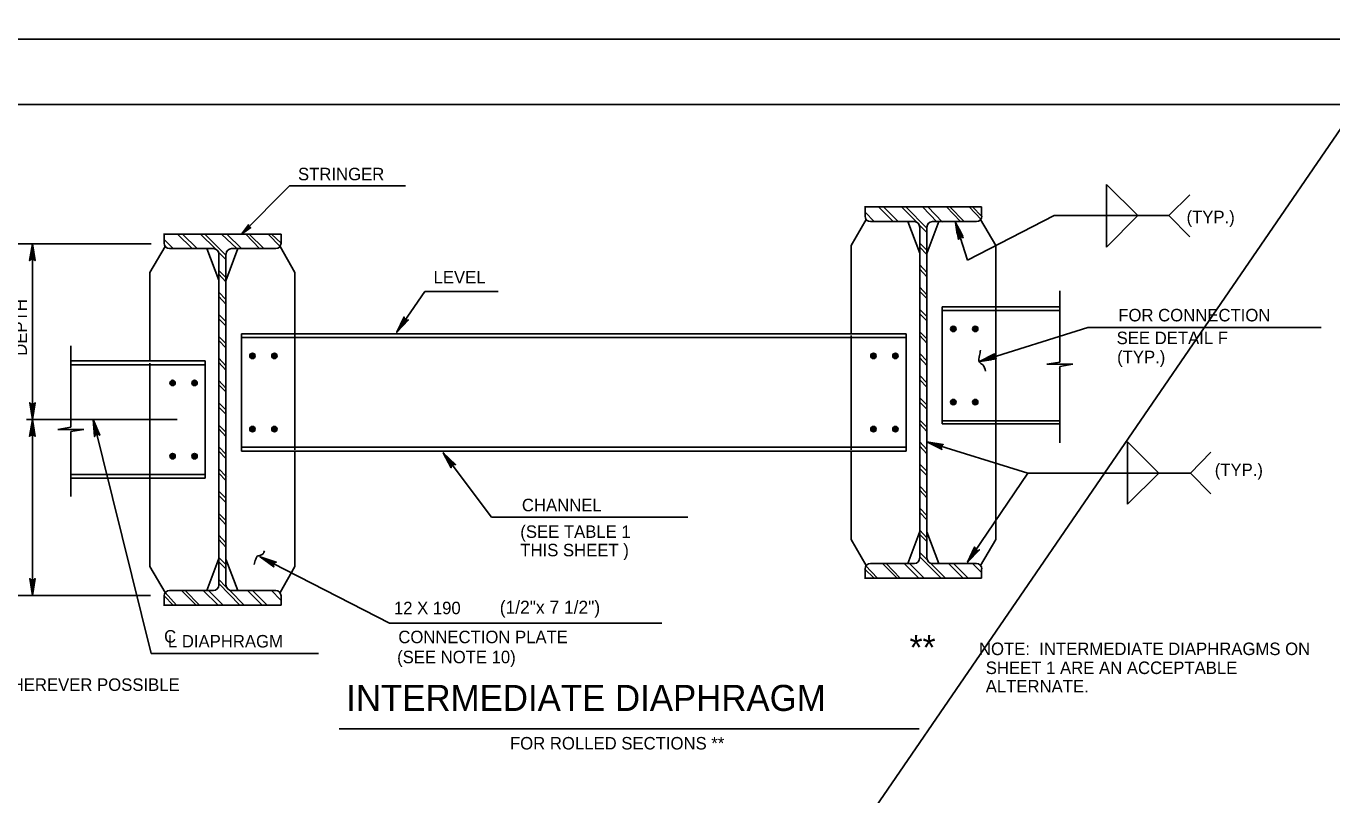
# Model space of a CAD drawing. Extents: x 634656 to 641360, y 298715 to 301183.
# Drawn here: x 640308.6 to 640609.6, y 299246 to 299423.1 of the extents above; entities that cross this region are included whole.
import ezdxf

# ---------------------------------------------------------------- set-up
doc = ezdxf.new("R2010")
doc.units = 0
for name, color, linetype in [('1', 7, 'Continuous'), ('2', 7, 'Continuous'), ('40', 7, 'Continuous')]:
    doc.layers.add(name, color=color, linetype=linetype)

msp = doc.modelspace()

# ---------------------------------------------------------------- linework, layer by layer
at = {"layer": '1'}
msp.add_line((641102.54, 300114.62), (640153.96, 298732.63), dxfattribs=at)
for points in [[(640309.53, 299369.26), (640309.79, 299369.4), (640309.99, 299372.95), (640309.53, 299369.26), (640309.36, 299369.07), (640309.99, 299372.95), (640310.16, 299369.4), (640310.43, 299369.27), (640309.99, 299372.95), (640310.6, 299369.07), (640310.43, 299369.27)], [(640396.47, 299355.35), (640396.17, 299355.38), (640393.99, 299352.58), (640396.47, 299355.35), (640396.71, 299355.41), (640393.99, 299352.58), (640395.87, 299355.59), (640395.72, 299355.85), (640393.99, 299352.58), (640395.69, 299356.12), (640395.72, 299355.85)], [(640310.45, 299336.14), (640310.18, 299336), (640309.99, 299332.45), (640310.45, 299336.14), (640310.61, 299336.33), (640309.99, 299332.45), (640309.81, 299336), (640309.55, 299336.13), (640309.99, 299332.45), (640309.37, 299336.33), (640309.55, 299336.13)], [(640309.53, 299328.76), (640309.79, 299328.9), (640309.99, 299332.45), (640309.53, 299328.76), (640309.36, 299328.57), (640309.99, 299332.45), (640310.16, 299328.9), (640310.43, 299328.77), (640309.99, 299332.45), (640310.6, 299328.57), (640310.43, 299328.77)], [(640324.43, 299328.76), (640324.65, 299328.96), (640323.99, 299332.45), (640324.43, 299328.76), (640324.32, 299328.54), (640323.99, 299332.45), (640325.01, 299329.05), (640325.3, 299328.99), (640323.99, 299332.45), (640325.52, 299328.83), (640325.3, 299328.99)], [(640406.58, 299321.59), (640406.71, 299321.86), (640404.74, 299324.83), (640406.58, 299321.59), (640406.56, 299321.34), (640404.74, 299324.83), (640407.01, 299322.09), (640407.29, 299322.14), (640404.74, 299324.83), (640407.56, 299322.09), (640407.29, 299322.14)], [(640365.56, 299298.74), (640365.56, 299299.04), (640362.49, 299300.83), (640365.56, 299298.74), (640365.66, 299298.51), (640362.49, 299300.83), (640365.73, 299299.37), (640365.97, 299299.54), (640362.49, 299300.83), (640366.22, 299299.61), (640365.97, 299299.54)], [(640310.45, 299295.64), (640310.18, 299295.5), (640309.99, 299291.95), (640310.45, 299295.64), (640310.61, 299295.83), (640309.99, 299291.95), (640309.81, 299295.5), (640309.55, 299295.63), (640309.99, 299291.95), (640309.37, 299295.83), (640309.55, 299295.63)]]:
    msp.add_lwpolyline(points, dxfattribs=at)
at = {"layer": '2'}
for p, q in [((640203.86, 299420.08), (641044.86, 299420.08)), ((640203.86, 299420.08), (641044.86, 299420.08)), ((640203.86, 299420.08), (641044.86, 299420.08)), ((640243.86, 299405.08), (641029.86, 299405.08)), ((640243.86, 299405.08), (641029.86, 299405.08)), ((640358.24, 299375.2), (640369.24, 299386.33)), ((640369.24, 299386.33), (640395.99, 299386.33)), ((640557.61, 299386.58), (640557.61, 299379.45)), ((640557.61, 299386.58), (640564.86, 299379.45)), ((640501.86, 299381.45), (640528.86, 299381.45)), ((640501.99, 299379.33), (640501.99, 299381.45)), ((640528.86, 299379.33), (640528.86, 299381.45)), ((640502.24, 299378.58), (640498.74, 299372.58)), ((640513.36, 299378.08), (640503.24, 299378.08)), ((640511.86, 299378.08), (640514.61, 299370.83)), ((640514.61, 299376.83), (640514.61, 299338.7)), ((640518.99, 299378.08), (640516.24, 299370.7)), ((640516.24, 299376.83), (640516.24, 299338.7)), ((640517.49, 299378.08), (640527.61, 299378.08)), ((640522.86, 299377.83), (640525.61, 299369.2)), ((640525.61, 299369.2), (640545.61, 299379.45)), ((640528.61, 299378.58), (640532.11, 299372.58)), ((640545.61, 299379.45), (640571.99, 299379.45)), ((640557.61, 299379.45), (640557.61, 299372.2)), ((640557.61, 299372.2), (640564.86, 299379.45)), ((640340.36, 299373.08), (640340.36, 299375.33)), ((640340.36, 299375.2), (640367.36, 299375.2)), ((640367.36, 299373.08), (640367.36, 299375.2)), ((640337.36, 299372.95), (640296.99, 299372.95)), ((640336.61, 299372.95), (640308.61, 299372.95)), ((640309.99, 299372.95), (640309.99, 299332.45)), ((640340.61, 299372.33), (640337.11, 299366.33)), ((640351.74, 299371.83), (640341.61, 299371.83)), ((640350.24, 299371.83), (640352.99, 299364.58)), ((640352.99, 299370.58), (640352.99, 299332.45)), ((640357.36, 299371.83), (640354.61, 299364.45)), ((640354.61, 299294.33), (640354.61, 299370.58)), ((640355.86, 299371.83), (640366.11, 299371.83)), ((640367.11, 299372.33), (640370.49, 299366.33)), ((640498.74, 299372.58), (640498.74, 299352.2)), ((640532.11, 299372.58), (640532.11, 299358.45)), ((640337.11, 299366.33), (640337.11, 299345.83)), ((640370.49, 299366.33), (640370.49, 299352.33)), ((640393.99, 299352.58), (640400.49, 299361.95)), ((640400.49, 299361.95), (640417.36, 299361.95)), ((640546.86, 299345.7), (640546.86, 299362.08)), ((640519.74, 299358.45), (640546.99, 299358.45)), ((640519.74, 299358.45), (640519.74, 299331.45)), ((640519.74, 299357.58), (640546.86, 299357.58)), ((640532.11, 299358.45), (640532.11, 299331.58)), ((640522.36, 299353.33), (640522.36, 299353.33)), ((640527.36, 299353.33), (640527.36, 299353.33)), ((640528.36, 299345.83), (640553.36, 299353.7)), ((640553.36, 299353.7), (640607.11, 299353.7)), ((640358.24, 299352.2), (640384.86, 299352.2)), ((640358.24, 299352.2), (640358.24, 299325.2)), ((640511.49, 299351.33), (640358.24, 299351.33)), ((640370.49, 299351.95), (640370.49, 299325.45)), ((640511.49, 299352.2), (640384.86, 299352.2)), ((640498.74, 299351.83), (640498.74, 299325.45)), ((640511.49, 299352.2), (640511.49, 299325.2)), ((640318.86, 299330.7), (640318.86, 299349.45)), ((640360.74, 299347.08), (640360.74, 299347.08)), ((640365.86, 299347.08), (640365.86, 299347.08)), ((640503.86, 299347.08), (640503.86, 299347.08)), ((640508.99, 299347.08), (640508.99, 299347.08)), ((640349.86, 299345.95), (640318.86, 299345.95)), ((640349.86, 299345.08), (640319.11, 299345.08)), ((640337.11, 299345.45), (640337.11, 299319.2)), ((640349.86, 299345.95), (640349.86, 299318.95)), ((640543.86, 299345.2), (640546.86, 299345.7)), ((640543.86, 299345.2), (640549.86, 299345.2)), ((640546.49, 299344.2), (640546.49, 299344.2)), ((640546.49, 299344.2), (640546.49, 299344.2)), ((640546.86, 299344.7), (640549.86, 299345.2)), ((640546.86, 299345.2), (640546.86, 299345.2)), ((640546.86, 299327.08), (640546.86, 299344.7)), ((640342.36, 299340.95), (640342.36, 299340.95)), ((640347.36, 299340.95), (640347.36, 299340.95)), ((640514.61, 299300.58), (640514.61, 299338.7)), ((640516.24, 299300.58), (640516.24, 299338.7)), ((640522.36, 299336.45), (640522.36, 299336.45)), ((640527.36, 299336.45), (640527.36, 299336.45)), ((640343.36, 299332.45), (640308.61, 299332.45)), ((640309.99, 299332.45), (640309.99, 299291.95)), ((640323.99, 299332.45), (640337.36, 299278.58)), ((640352.99, 299294.33), (640352.99, 299332.45)), ((640519.74, 299332.2), (640546.86, 299332.2)), ((640519.74, 299331.45), (640546.86, 299331.45)), ((640315.86, 299330.2), (640318.86, 299330.7)), ((640315.86, 299330.2), (640321.86, 299330.2)), ((640318.86, 299329.7), (640321.86, 299330.2)), ((640318.86, 299330.2), (640318.86, 299330.2)), ((640318.86, 299314.7), (640318.86, 299329.7)), ((640360.74, 299330.2), (640360.74, 299330.2)), ((640365.86, 299330.2), (640365.86, 299330.2)), ((640503.86, 299330.2), (640503.86, 299330.2)), ((640508.99, 299330.2), (640508.99, 299330.2)), ((640532.11, 299331.33), (640532.11, 299304.83)), ((640511.49, 299326.08), (640358.24, 299326.08)), ((640516.24, 299327.33), (640539.49, 299320.08)), ((640562.49, 299327.33), (640562.49, 299320.08)), ((640562.49, 299327.33), (640569.74, 299320.08)), ((640342.36, 299324.08), (640342.36, 299324.08)), ((640347.36, 299324.08), (640347.36, 299324.08)), ((640358.24, 299325.2), (640384.86, 299325.2)), ((640370.49, 299325.08), (640370.49, 299298.58)), ((640511.49, 299325.2), (640383.99, 299325.2)), ((640404.74, 299324.83), (640415.86, 299309.95)), ((640498.74, 299325.2), (640498.74, 299304.83)), ((640349.86, 299319.83), (640319.11, 299319.83)), ((640539.49, 299320.08), (640525.61, 299299.58)), ((640539.49, 299320.08), (640576.99, 299320.08)), ((640562.49, 299320.08), (640562.49, 299312.95)), ((640562.49, 299312.95), (640569.74, 299320.08)), ((640349.86, 299318.95), (640318.99, 299318.95)), ((640337.11, 299318.95), (640337.11, 299298.58)), ((640354.99, 299319.33), (640354.99, 299319.33)), ((640415.86, 299309.95), (640461.11, 299309.95)), ((640502.24, 299298.83), (640498.74, 299304.83)), ((640511.86, 299299.33), (640514.61, 299306.7)), ((640518.99, 299299.33), (640516.24, 299306.58)), ((640528.61, 299298.83), (640532.11, 299304.83)), ((640340.61, 299292.58), (640337.11, 299298.58)), ((640350.24, 299293.08), (640352.99, 299300.45)), ((640357.36, 299293.08), (640354.61, 299300.33)), ((640362.49, 299300.83), (640392.36, 299285.58)), ((640367.11, 299292.58), (640370.49, 299298.58)), ((640513.36, 299299.33), (640503.24, 299299.33)), ((640517.49, 299299.33), (640527.61, 299299.33)), ((640501.86, 299295.95), (640528.86, 299295.95)), ((640501.99, 299298.08), (640501.99, 299295.83)), ((640528.86, 299298.08), (640528.86, 299295.95)), ((640351.74, 299293.08), (640341.61, 299293.08)), ((640355.86, 299293.08), (640366.11, 299293.08)), ((640337.24, 299291.95), (640296.99, 299291.95)), ((640340.36, 299291.83), (640340.36, 299289.58)), ((640340.36, 299289.7), (640367.36, 299289.7)), ((640367.36, 299291.83), (640367.36, 299289.7)), ((640392.36, 299285.58), (640455.13, 299285.58)), ((640337.36, 299278.58), (640375.99, 299278.58)), ((640380.74, 299261.2), (640514.49, 299261.2))]:
    msp.add_line(p, q, dxfattribs=at)
for points in [[(640576.86, 299384.2), (640571.99, 299379.45), (640576.86, 299374.58)], [(640504.11, 299378.08), (640501.99, 299380.2)], [(640508.49, 299378.08), (640505.11, 299381.45)], [(640509.61, 299378.08), (640506.24, 299381.45)], [(640513.74, 299378.08), (640510.36, 299381.45)], [(640516.24, 299376.58), (640511.36, 299381.45)], [(640518.61, 299377.95), (640515.24, 299381.45)], [(640519.86, 299377.95), (640516.49, 299381.45)], [(640523.99, 299378.08), (640520.74, 299381.45)], [(640524.86, 299378.08), (640521.49, 299381.45)], [(640528.74, 299378.58), (640525.99, 299381.45)], [(640528.86, 299379.33), (640526.74, 299381.45)], [(640360.24, 299376.7), (640359.99, 299376.83), (640358.24, 299375.2), (640360.24, 299376.7), (640360.36, 299376.7), (640358.24, 299375.2), (640359.86, 299376.95), (640359.74, 299377.2), (640358.24, 299375.2), (640359.86, 299377.33), (640359.74, 299377.2)], [(640516.24, 299375.58), (640514.61, 299377.2)], [(640523.36, 299375.33), (640523.49, 299375.45), (640522.86, 299377.83), (640523.36, 299375.33), (640523.24, 299375.2), (640522.86, 299377.83), (640523.74, 299375.58), (640523.86, 299375.58), (640522.86, 299377.83), (640524.11, 299375.45), (640523.86, 299375.58)], [(640523.49, 299374.58), (640523.74, 299374.7), (640522.86, 299377.83), (640523.49, 299374.58), (640523.49, 299374.33), (640522.86, 299377.83), (640523.99, 299374.83), (640524.24, 299374.83), (640522.86, 299377.83), (640524.49, 299374.7), (640524.24, 299374.83)], [(640523.61, 299374.2), (640523.74, 299374.45), (640522.86, 299377.83), (640523.61, 299374.2), (640523.49, 299373.95), (640522.86, 299377.83), (640524.11, 299374.58), (640524.36, 299374.45), (640522.86, 299377.83), (640524.61, 299374.33), (640524.36, 299374.45)], [(640342.49, 299371.83), (640340.36, 299373.95)], [(640346.86, 299371.83), (640343.49, 299375.2)], [(640347.99, 299371.83), (640344.61, 299375.2)], [(640352.11, 299371.83), (640348.74, 299375.2)], [(640354.61, 299370.33), (640349.74, 299375.2)], [(640357.11, 299371.83), (640353.61, 299375.2)], [(640358.24, 299371.83), (640354.86, 299375.2)], [(640362.36, 299371.83), (640359.24, 299375.2)], [(640363.36, 299371.83), (640359.99, 299375.2)], [(640367.11, 299372.33), (640364.36, 299375.2)], [(640367.36, 299373.08), (640365.11, 299375.2)], [(640354.61, 299369.33), (640352.99, 299370.95)], [(640516.24, 299371.45), (640514.61, 299373.08)], [(640514.61, 299372.2), (640516.24, 299370.45)], [(640516.24, 299366.33), (640514.61, 299368.08)], [(640354.61, 299365.2), (640352.99, 299366.83)], [(640352.99, 299365.95), (640354.61, 299364.2)], [(640516.24, 299365.33), (640514.61, 299367.08)], [(640354.61, 299360.08), (640352.99, 299361.83)], [(640516.24, 299361.2), (640514.61, 299362.95)], [(640516.24, 299360.33), (640514.61, 299361.95)], [(640354.61, 299359.08), (640352.99, 299360.83)], [(640354.61, 299355.08), (640352.99, 299356.7)], [(640354.61, 299354.08), (640352.99, 299355.7)], [(640516.24, 299356.2), (640514.61, 299357.83)], [(640516.24, 299355.2), (640514.61, 299356.83)], [(640516.24, 299351.08), (640514.61, 299352.7)], [(640354.61, 299349.95), (640352.99, 299351.58)], [(640354.61, 299348.95), (640352.99, 299350.7)], [(640516.24, 299350.08), (640514.61, 299351.83)], [(640354.61, 299344.83), (640352.99, 299346.58)], [(640516.24, 299345.95), (640514.61, 299347.7)], [(640516.24, 299344.95), (640514.61, 299346.7)], [(640531.99, 299346.45), (640531.86, 299346.7), (640528.36, 299345.83), (640531.99, 299346.45), (640532.24, 299346.45), (640528.36, 299345.83), (640531.74, 299347.08), (640531.74, 299347.33), (640528.36, 299345.83), (640531.86, 299347.58), (640531.74, 299347.33)], [(640530.86, 299346.33), (640530.74, 299346.45), (640528.49, 299345.83), (640530.86, 299346.33), (640530.99, 299346.2), (640528.49, 299345.83), (640530.61, 299346.7), (640530.74, 299346.83), (640528.49, 299345.83), (640530.74, 299346.95), (640530.74, 299346.83)], [(640354.61, 299343.83), (640352.99, 299345.58)], [(640354.61, 299339.7), (640352.99, 299341.45)], [(640354.61, 299338.83), (640352.99, 299340.45)], [(640516.24, 299340.95), (640514.61, 299342.58)], [(640516.24, 299339.95), (640514.61, 299341.58)], [(640516.24, 299335.83), (640514.61, 299337.45)], [(640354.61, 299334.7), (640352.99, 299336.33)], [(640354.61, 299333.7), (640352.99, 299335.33)], [(640516.24, 299334.83), (640514.61, 299336.45)], [(640516.24, 299330.7), (640514.61, 299332.33)], [(640516.24, 299329.7), (640514.61, 299331.45)], [(640354.61, 299329.58), (640352.99, 299331.2)], [(640354.61, 299328.58), (640352.99, 299330.33)], [(640354.61, 299324.45), (640352.99, 299326.2)], [(640516.24, 299325.58), (640514.61, 299327.33)], [(640516.24, 299324.58), (640514.61, 299326.33)], [(640519.49, 299325.7), (640519.49, 299326.08), (640516.24, 299327.33), (640519.49, 299325.7), (640519.74, 299325.58), (640516.24, 299327.33), (640519.61, 299326.45), (640519.86, 299326.58), (640516.24, 299327.33), (640519.99, 299326.7), (640519.86, 299326.58)], [(640354.61, 299323.45), (640352.99, 299325.2)], [(640581.74, 299324.95), (640576.99, 299320.08), (640581.74, 299315.33)], [(640354.61, 299319.45), (640352.99, 299321.08)], [(640354.61, 299318.45), (640352.99, 299320.08)], [(640516.24, 299320.58), (640514.61, 299322.2)], [(640516.24, 299319.58), (640514.61, 299321.2)], [(640516.24, 299315.45), (640514.61, 299317.08)], [(640354.61, 299314.33), (640352.99, 299315.95)], [(640354.61, 299313.33), (640352.99, 299314.95)], [(640516.24, 299314.45), (640514.61, 299316.2)], [(640354.61, 299309.2), (640352.99, 299310.83)], [(640516.24, 299310.33), (640514.61, 299312.08)], [(640516.24, 299309.33), (640514.61, 299311.08)], [(640354.61, 299308.2), (640352.99, 299309.95)], [(640354.61, 299304.08), (640352.99, 299305.83)], [(640354.61, 299303.08), (640352.99, 299304.83)], [(640516.24, 299305.2), (640514.61, 299306.95)], [(640516.24, 299304.33), (640514.61, 299305.95)], [(640516.24, 299300.2), (640514.61, 299301.83)], [(640528.11, 299302.33), (640527.74, 299302.33), (640525.61, 299299.58), (640528.11, 299302.33), (640528.36, 299302.45), (640525.61, 299299.58), (640527.49, 299302.58), (640527.36, 299302.83), (640525.61, 299299.58), (640527.24, 299303.08), (640527.36, 299302.83)], [(640354.61, 299299.08), (640352.99, 299300.7)], [(640354.61, 299298.08), (640352.99, 299299.7)], [(640502.11, 299298.83), (640504.86, 299295.95)], [(640505.99, 299299.33), (640509.36, 299295.95)], [(640506.86, 299299.33), (640510.11, 299295.95)], [(640510.99, 299299.33), (640514.36, 299295.95)], [(640512.24, 299299.33), (640515.61, 299295.95)], [(640519.49, 299295.95), (640514.61, 299300.83)], [(640517.11, 299299.33), (640520.49, 299295.95)], [(640521.24, 299299.33), (640524.61, 299295.95)], [(640522.36, 299299.33), (640525.74, 299295.95)], [(640526.74, 299299.33), (640528.86, 299297.2)], [(640354.61, 299293.95), (640352.99, 299295.58)], [(640501.86, 299298.08), (640504.11, 299295.95)], [(640340.61, 299292.58), (640343.24, 299289.7)], [(640344.36, 299293.08), (640347.74, 299289.7)], [(640345.24, 299293.08), (640348.49, 299289.7)], [(640349.36, 299293.08), (640352.86, 299289.7)], [(640350.61, 299293.08), (640353.99, 299289.7)], [(640357.86, 299289.7), (640352.99, 299294.7)], [(640355.49, 299293.08), (640358.86, 299289.7)], [(640359.61, 299293.08), (640362.99, 299289.7)], [(640360.74, 299293.08), (640364.11, 299289.7)], [(640365.11, 299293.08), (640367.24, 299290.95)], [(640340.36, 299291.83), (640342.49, 299289.7)]]:
    msp.add_lwpolyline(points, dxfattribs=at)
for centre, radius in [((640522.33, 299353.35), 0.624), ((640522.33, 299353.35), 0.446), ((640522.33, 299353.35), 0.244), ((640522.33, 299353.35), 0.123), ((640522.33, 299353.35), 0.0527), ((640527.39, 299353.35), 0.624), ((640527.39, 299353.35), 0.446), ((640527.39, 299353.35), 0.244), ((640527.39, 299353.35), 0.123), ((640527.39, 299353.35), 0.0527), ((640360.74, 299347.13), 0.624), ((640360.74, 299347.13), 0.446), ((640360.74, 299347.13), 0.244), ((640360.74, 299347.13), 0.123), ((640360.74, 299347.13), 0.0527), ((640365.8, 299347.13), 0.624), ((640365.8, 299347.13), 0.446), ((640365.8, 299347.13), 0.244), ((640365.8, 299347.13), 0.123), ((640365.8, 299347.13), 0.0527), ((640503.92, 299347.13), 0.624), ((640503.92, 299347.13), 0.446), ((640503.92, 299347.13), 0.244), ((640503.92, 299347.13), 0.123), ((640503.92, 299347.13), 0.0527), ((640508.98, 299347.13), 0.624), ((640508.98, 299347.13), 0.446), ((640508.98, 299347.13), 0.244), ((640508.98, 299347.13), 0.123), ((640508.98, 299347.13), 0.0527), ((640342.33, 299340.9), 0.624), ((640342.33, 299340.9), 0.446), ((640342.33, 299340.9), 0.244), ((640342.33, 299340.9), 0.123), ((640342.33, 299340.9), 0.0527), ((640347.39, 299340.9), 0.624), ((640347.39, 299340.9), 0.446), ((640347.39, 299340.9), 0.244), ((640347.39, 299340.9), 0.123), ((640347.39, 299340.9), 0.0527), ((640522.33, 299336.48), 0.624), ((640522.33, 299336.48), 0.446), ((640522.33, 299336.48), 0.244), ((640522.33, 299336.48), 0.123), ((640522.33, 299336.48), 0.0527), ((640527.39, 299336.48), 0.624), ((640527.39, 299336.48), 0.446), ((640527.39, 299336.48), 0.244), ((640527.39, 299336.48), 0.123), ((640527.39, 299336.48), 0.0527), ((640360.74, 299330.25), 0.624), ((640360.74, 299330.25), 0.446), ((640360.74, 299330.25), 0.244), ((640360.74, 299330.25), 0.123), ((640360.74, 299330.25), 0.0527), ((640365.8, 299330.25), 0.624), ((640365.8, 299330.25), 0.446), ((640365.8, 299330.25), 0.244), ((640365.8, 299330.25), 0.123), ((640365.8, 299330.25), 0.0527), ((640503.92, 299330.25), 0.624), ((640503.92, 299330.25), 0.446), ((640503.92, 299330.25), 0.244), ((640503.92, 299330.25), 0.123), ((640503.92, 299330.25), 0.0527), ((640508.98, 299330.25), 0.624), ((640508.98, 299330.25), 0.446), ((640508.98, 299330.25), 0.244), ((640508.98, 299330.25), 0.123), ((640508.98, 299330.25), 0.0527), ((640342.33, 299324.02), 0.624), ((640342.33, 299324.02), 0.446), ((640342.33, 299324.02), 0.244), ((640342.33, 299324.02), 0.123), ((640342.33, 299324.02), 0.0527), ((640347.39, 299324.02), 0.624), ((640347.39, 299324.02), 0.446), ((640347.39, 299324.02), 0.244), ((640347.39, 299324.02), 0.123), ((640347.39, 299324.02), 0.0527)]:
    msp.add_circle(centre, radius, dxfattribs=at)
for centre, start, end in [((640503.23, 299379.31), 180, 270), ((640513.32, 299376.81), 0, 90), ((640517.51, 299376.81), 90, 180), ((640527.67, 299379.31), 270, 0), ((640341.64, 299373.09), 180, 270), ((640351.73, 299370.59), 0, 90), ((640355.92, 299370.59), 90, 180), ((640366.08, 299373.09), 270, 0), ((640503.23, 299298.05), 90, 180), ((640513.32, 299300.56), 270, 0), ((640517.51, 299300.55), 180, 270), ((640527.67, 299298.05), 0, 90), ((640341.64, 299291.83), 90, 180), ((640351.73, 299294.33), 270, 0), ((640355.92, 299294.33), 180, 270), ((640366.08, 299291.83), 0, 90)]:
    msp.add_arc(centre, 1.25, start, end, dxfattribs=at)
for points in [[(640528.61, 299348.45), (640528.36, 299347.2), (640528.36, 299345.7), (640529.11, 299345.08), (640529.74, 299343.58)], [(640361.11, 299299.08), (640361.49, 299300.33), (640361.86, 299300.95), (640362.61, 299301.2), (640363.24, 299301.58), (640363.49, 299302.2)]]:
    msp.add_spline(points, degree=3, dxfattribs=at)

# ---------------------------------------------------------------- texts
for s, height, p in [('STRINGER', 2.879, (640371.24, 299387.58)), ('(TYP.)', 2.875, (640576.11, 299377.7)), ('LEVEL', 2.879, (640402.49, 299363.83)), ('FOR CONNECTION', 2.8792, (640560.36, 299355.08)), ('SEE DETAIL F', 2.88, (640559.98, 299349.83)), ('(TYP.)', 2.875, (640560.1, 299345.45)), ('(TYP.)', 2.875, (640582.61, 299319.45)), ('CHANNEL', 2.879, (640422.86, 299311.33)), ('(SEE TABLE 1', 2.8792, (640422.49, 299305.2)), ('THIS SHEET )', 2.8792, (640422.49, 299300.95)), ('12 X 190', 2.875, (640393.36, 299287.62)), ('C', 2.88, (640340.36, 299281.08)), ('CONNECTION PLATE', 2.8748, (640394.37, 299280.94)), ('L DIAPHRAGM', 2.8792, (640341.24, 299279.95)), ('**', 5.759, (640512.24, 299277.08)), ('NOTE:  INTERMEDIATE DIAPHRAGMS ON', 2.8792, (640528.24, 299278.2)), ('(SEE NOTE 10)', 2.8748, (640394.09, 299276.32)), ('          SHEET 1 ARE AN ACCEPTABLE', 2.88, (640519.11, 299273.83)), ('- WHEREVER POSSIBLE', 2.8792, (640299.24, 299269.95)), ('INTERMEDIATE DIAPHRAGM', 6, (640382.36, 299265.33)), ('          ALTERNATE.', 2.8792, (640519.11, 299269.58)), ('FOR ROLLED SECTIONS **', 2.8792, (640420.11, 299256.45))]:
    msp.add_text(s, height=height, dxfattribs=at).set_placement(p)
msp.add_text(' DEPTH ', height=2.88, rotation=90, dxfattribs=at).set_placement((640308.74, 299346.08))
at = {"layer": '40'}
msp.add_text('(1/2"x 7 1/2")', height=3, dxfattribs=at).set_placement((640417.76, 299287.72))

doc.saveas('drawing.dxf')
